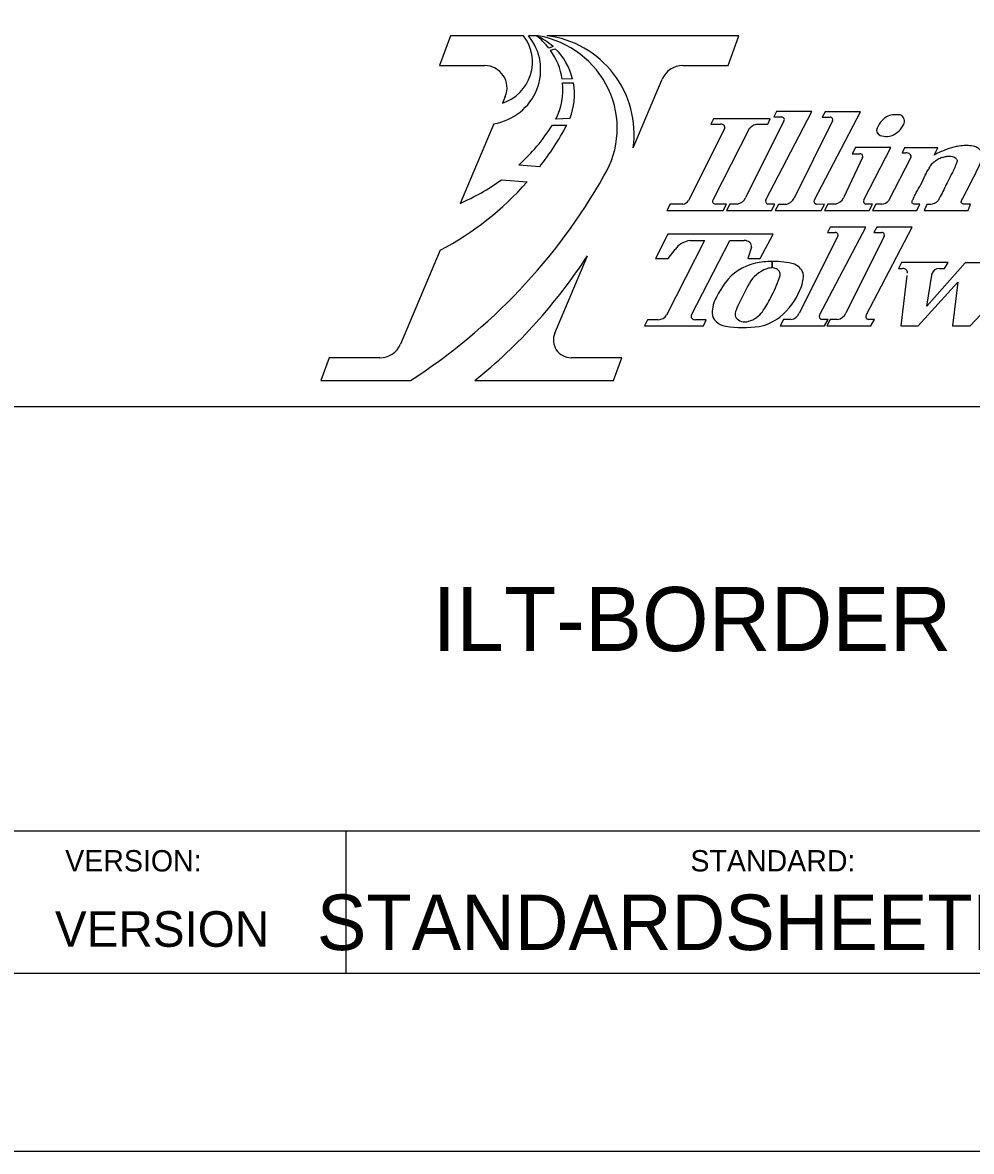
# Model space of a CAD drawing. Extents: x -0.22 to 2.83, y -0.07 to 1.83.
# Drawn here: x 2.4415 to 2.6636, y 0 to 0.2643 of the extents above; entities that cross this region are included whole.
import ezdxf

# ---------------------------------------------------------------- set-up
doc = ezdxf.new("R2010")
doc.units = 0
for name, color, linetype in [('SH_General_Details', 7, 'Continuous'), ('SH_General_Details_Sheet_Standard-ILTollway', 7, 'Continuous'), ('SH_General_Details_Title_Text-ILTollway', 7, 'Continuous'), ('SH_General_Details_Version_Text-ILTollway', 7, 'Continuous'), ('SH_Printer Plotting Border-ILTollway', 7, 'Continuous'), ('Sheets_General Details - Revisions', 7, 'Continuous')]:
    doc.layers.add(name, color=color, linetype=linetype)

msp = doc.modelspace()

# ---------------------------------------------------------------- linework, layer by layer
at = {"layer": 'SH_General_Details'}
for p, q in [((2.541678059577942, 0.26125465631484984), (2.5391048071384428, 0.25424934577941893)), ((2.558770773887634, 0.26125307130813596), (2.541678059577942, 0.26125465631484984)), ((2.5617576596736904, 0.2612526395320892), (2.5599128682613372, 0.2612529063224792)), ((2.5622159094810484, 0.26125257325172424), (2.5617576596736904, 0.2612526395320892)), ((2.6092131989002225, 0.2612457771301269), (2.564246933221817, 0.26125227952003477)), ((2.6066432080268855, 0.25424934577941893), (2.6092131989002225, 0.2612457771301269)), ((2.5656805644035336, 0.2587088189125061), (2.564693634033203, 0.2583604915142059)), ((2.5650607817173, 0.2578687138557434), (2.5662091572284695, 0.25821166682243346)), ((2.5391048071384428, 0.25424934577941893), (2.5496910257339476, 0.25424934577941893)), ((2.5960569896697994, 0.25424934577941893), (2.6066432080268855, 0.25424934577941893)), ((2.570235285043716, 0.25119200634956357), (2.567815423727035, 0.251082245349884)), ((2.567924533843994, 0.2501808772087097), (2.5704507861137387, 0.25021086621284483)), ((2.584443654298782, 0.23498173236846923), (2.5912613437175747, 0.25107288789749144)), ((2.5544875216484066, 0.2470111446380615), (2.5538310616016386, 0.24545995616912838)), ((2.551788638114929, 0.24063379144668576), (2.5439024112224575, 0.221998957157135)), ((2.569615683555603, 0.24183801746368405), (2.5663216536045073, 0.24171894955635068)), ((2.616512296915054, 0.24179491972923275), (2.6032718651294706, 0.24179491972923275)), ((2.6197487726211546, 0.2413310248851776), (2.610752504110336, 0.22328553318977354)), ((2.615985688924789, 0.24053008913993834), (2.616512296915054, 0.24179491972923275)), ((2.6311086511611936, 0.24128882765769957), (2.622112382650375, 0.2232433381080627)), ((2.5655231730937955, 0.24031608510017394), (2.5688893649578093, 0.24028897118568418)), ((2.6058492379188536, 0.23947303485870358), (2.5973743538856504, 0.22265382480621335)), ((2.603179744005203, 0.22279209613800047), (2.6117820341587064, 0.23965211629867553)), ((2.613987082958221, 0.24053468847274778), (2.615985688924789, 0.24053008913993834)), ((2.6381201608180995, 0.23271397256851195), (2.633689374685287, 0.22326657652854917)), ((2.6494769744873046, 0.23273907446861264), (2.6442469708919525, 0.2225763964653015)), ((2.647989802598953, 0.2350050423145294), (2.6474070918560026, 0.23379013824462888)), ((2.6474070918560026, 0.23379013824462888), (2.648289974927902, 0.23379013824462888)), ((2.655788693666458, 0.2350050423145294), (2.647989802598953, 0.2350050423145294)), ((2.6549143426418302, 0.233294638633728), (2.655788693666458, 0.2350050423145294)), ((2.56256064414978, 0.23056123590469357), (2.5576849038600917, 0.23094110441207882)), ((2.5535774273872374, 0.22753960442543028), (2.559652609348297, 0.22704168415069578)), ((2.6615555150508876, 0.22308809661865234), (2.6636318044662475, 0.22710824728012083)), ((2.5931374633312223, 0.22180414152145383), (2.59234472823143, 0.22033744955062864)), ((2.59234472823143, 0.22033744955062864), (2.605503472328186, 0.22033744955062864)), ((2.5960391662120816, 0.2218161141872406), (2.5931374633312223, 0.22180414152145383)), ((2.6062812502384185, 0.22180450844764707), (2.603693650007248, 0.22180450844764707)), ((2.605503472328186, 0.22033744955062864), (2.6062812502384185, 0.22180450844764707)), ((2.607087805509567, 0.2218036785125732), (2.6062950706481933, 0.22033698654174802)), ((2.6062950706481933, 0.22033698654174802), (2.6168223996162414, 0.22032778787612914)), ((2.608808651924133, 0.2218008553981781), (2.607087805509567, 0.2218036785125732)), ((2.6176034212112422, 0.22180262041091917), (2.6160084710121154, 0.22181677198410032)), ((2.6168223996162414, 0.22032778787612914), (2.6176034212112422, 0.22180262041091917)), ((2.618447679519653, 0.2217614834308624), (2.6176549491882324, 0.22029479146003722)), ((2.6176549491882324, 0.22029479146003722), (2.6284404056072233, 0.22029142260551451)), ((2.6201685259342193, 0.22175866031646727), (2.618447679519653, 0.2217614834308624)), ((2.6292331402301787, 0.2217581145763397), (2.6273683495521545, 0.2217745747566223)), ((2.6284404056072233, 0.22029142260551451), (2.6292331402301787, 0.2217581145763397)), ((2.6300077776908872, 0.22183038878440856), (2.629215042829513, 0.22036369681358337)), ((2.629231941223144, 0.22031802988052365), (2.6397115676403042, 0.22031637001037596)), ((2.6317455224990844, 0.22178189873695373), (2.6300246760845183, 0.22178472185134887)), ((2.640502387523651, 0.22178071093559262), (2.6389453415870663, 0.22179781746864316)), ((2.6397115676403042, 0.22031637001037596), (2.640502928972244, 0.22178052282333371)), ((2.6412836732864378, 0.22180444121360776), (2.6404826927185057, 0.22033670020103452)), ((2.6404826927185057, 0.22033670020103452), (2.650853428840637, 0.22033670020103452)), ((2.642634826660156, 0.22180444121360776), (2.6412836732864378, 0.22180444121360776)), ((2.6515525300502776, 0.221801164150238), (2.6502094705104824, 0.221801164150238)), ((2.650853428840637, 0.22033670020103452), (2.6515525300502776, 0.221801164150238)), ((2.6531976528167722, 0.22174590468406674), (2.652547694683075, 0.22033670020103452)), ((2.652547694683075, 0.22033670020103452), (2.662856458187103, 0.22033670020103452)), ((2.6634214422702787, 0.2218007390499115), (2.6617628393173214, 0.22181180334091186)), ((2.662856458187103, 0.22033670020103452), (2.6634214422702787, 0.2218007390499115)), ((2.6323300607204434, 0.21430038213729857), (2.6233337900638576, 0.19625489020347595)), ((2.6432246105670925, 0.21430038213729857), (2.6342283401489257, 0.19625489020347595)), ((2.598115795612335, 0.1958784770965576), (2.6070817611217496, 0.2133110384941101)), ((2.6070817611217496, 0.2133110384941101), (2.610442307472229, 0.2133110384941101)), ((2.5392720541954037, 0.21105761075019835), (2.529944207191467, 0.18901628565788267)), ((2.5660758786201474, 0.19162998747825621), (2.573748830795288, 0.20973973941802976)), ((2.592641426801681, 0.20907231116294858), (2.594264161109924, 0.21120603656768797)), ((2.6170039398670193, 0.2083940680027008), (2.6170039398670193, 0.20687558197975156)), ((2.6170039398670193, 0.20687558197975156), (2.6170039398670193, 0.2083940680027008)), ((2.6666739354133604, 0.2080908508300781), (2.6621581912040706, 0.2080908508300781)), ((2.663346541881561, 0.19334409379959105), (2.6746359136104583, 0.20542692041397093)), ((2.6196690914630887, 0.19477303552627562), (2.6188763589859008, 0.193306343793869)), ((2.6188763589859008, 0.193306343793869), (2.6292116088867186, 0.19333077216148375)), ((2.6213899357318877, 0.19477021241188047), (2.6196690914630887, 0.19477303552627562)), ((2.630071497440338, 0.19479352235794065), (2.6285897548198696, 0.1947861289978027)), ((2.6292116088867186, 0.19333077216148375), (2.630071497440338, 0.19479352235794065)), ((2.6305636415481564, 0.19477303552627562), (2.6297709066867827, 0.193306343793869)), ((2.6297709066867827, 0.193306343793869), (2.6401061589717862, 0.19333077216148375)), ((2.6322844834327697, 0.19477021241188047), (2.6305636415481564, 0.19477303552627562)), ((2.6409660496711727, 0.19479352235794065), (2.639484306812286, 0.1947861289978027)), ((2.6401061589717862, 0.19333077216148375), (2.6409660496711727, 0.19479352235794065)), ((2.6591873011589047, 0.19334409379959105), (2.663346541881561, 0.19334409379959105)), ((2.513288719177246, 0.18583782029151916), (2.5113223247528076, 0.1804845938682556)), ((2.5251477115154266, 0.18583782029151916), (2.513288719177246, 0.18583782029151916)), ((2.581771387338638, 0.18583782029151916), (2.5699123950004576, 0.18583782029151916)), ((2.579804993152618, 0.1804845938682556), (2.581771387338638, 0.18583782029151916)), ((2.5113223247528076, 0.1804845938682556), (2.53227757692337, 0.1804845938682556)), ((2.547344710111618, 0.1804845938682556), (2.579804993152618, 0.1804845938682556)), ((2.7916666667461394, 0.17433751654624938), (2.4316674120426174, 0.17433751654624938)), ((2.7916666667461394, 0.07499986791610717), (2.4316674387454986, 0.07499986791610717)), ((2.517257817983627, 0.04166668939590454), (2.517257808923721, 0.07499986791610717))]:
    msp.add_line(p, q, dxfattribs=at)
msp.add_lwpolyline([(0.1666666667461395, 0.0416666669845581), (0.1666666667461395, 1.791666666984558), (2.7916666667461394, 1.791666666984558), (2.7916666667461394, 0.0416666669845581)], close=True, dxfattribs=at)
for points in [[(2.6155131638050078, 0.22285597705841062), (2.6262976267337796, 0.2434896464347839), (2.61800227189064, 0.2434869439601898)], [(2.61800227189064, 0.2434869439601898), (2.6173446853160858, 0.24223627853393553), (2.6191797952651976, 0.24223627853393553)], [(2.626873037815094, 0.22281378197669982), (2.6376575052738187, 0.24344744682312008), (2.629362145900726, 0.24344474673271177)], [(2.629362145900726, 0.24344474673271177), (2.628704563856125, 0.2421940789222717)], [(2.5663006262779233, 0.2417181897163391), (2.5663148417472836, 0.24171870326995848), (2.5663184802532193, 0.24171883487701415)], [(2.5663216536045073, 0.24171894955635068), (2.5663150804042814, 0.2417120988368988)], [(2.5663184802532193, 0.24171883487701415), (2.5663216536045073, 0.24171894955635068)], [(2.6032718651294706, 0.24179491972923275), (2.6026142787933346, 0.2405442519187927)], [(2.6026142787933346, 0.2405442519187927), (2.6048686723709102, 0.2405442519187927)], [(2.628704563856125, 0.2421940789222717), (2.6305396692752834, 0.2421940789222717)], [(2.636509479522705, 0.23505239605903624), (2.6357160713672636, 0.23361922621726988), (2.6375511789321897, 0.23361922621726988)], [(2.638450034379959, 0.22283702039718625), (2.644804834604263, 0.23505509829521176), (2.636509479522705, 0.23505239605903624)], [(2.612125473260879, 0.21171108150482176), (2.6113013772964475, 0.20911943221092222), (2.6141857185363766, 0.20911943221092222), (2.6171877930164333, 0.21477393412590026), (2.5925825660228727, 0.21477393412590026), (2.5896982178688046, 0.20907231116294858), (2.592641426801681, 0.20907231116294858)], [(2.6280944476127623, 0.19582533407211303), (2.6388789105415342, 0.21645900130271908), (2.6305835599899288, 0.21645630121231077)], [(2.6305835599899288, 0.21645630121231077), (2.629925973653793, 0.2152056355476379), (2.6317610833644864, 0.2152056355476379)], [(2.6389889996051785, 0.19582533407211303), (2.649773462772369, 0.21645900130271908), (2.641478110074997, 0.21645630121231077)], [(2.641478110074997, 0.21645630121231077), (2.6408205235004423, 0.2152056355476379), (2.6426556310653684, 0.2152056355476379)], [(2.5977626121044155, 0.21331319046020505), (2.601117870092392, 0.21331319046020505), (2.592229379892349, 0.19583135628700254)], [(2.6473037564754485, 0.20813842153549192), (2.64659074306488, 0.20675888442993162), (2.6474820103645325, 0.20675888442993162)], [(2.6560975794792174, 0.20675888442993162), (2.657345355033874, 0.20675888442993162), (2.6581772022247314, 0.20813842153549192), (2.6473037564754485, 0.20813842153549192)], [(2.6621581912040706, 0.2080908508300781), (2.6531861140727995, 0.1979108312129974)], [(2.6485515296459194, 0.20509393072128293), (2.6471255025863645, 0.19334409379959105), (2.651165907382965, 0.19334409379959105)], [(2.6531861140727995, 0.1979108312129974), (2.6544338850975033, 0.20561720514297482)], [(2.651165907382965, 0.19334409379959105), (2.660435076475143, 0.20352411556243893), (2.6591873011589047, 0.19334409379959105)], [(2.5902868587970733, 0.19474757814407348), (2.5877556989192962, 0.19474757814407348), (2.5871081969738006, 0.19333395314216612), (2.6008824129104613, 0.19333395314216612), (2.601529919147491, 0.19474757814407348), (2.5989987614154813, 0.19474757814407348)]]:
    msp.add_lwpolyline(points, dxfattribs=at)
for centre, radius, start, end in [((2.5507281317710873, 0.255099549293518), 0.010126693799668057, 287.8430702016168, 37.42003830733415), ((2.5556024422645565, 0.24746375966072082), 0.01510032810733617, 48.13245664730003, 65.94449523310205), ((2.5523351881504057, 0.24875107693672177), 0.015654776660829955, 37.86715463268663, 52.99453830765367), ((2.5614015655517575, 0.23816590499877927), 0.02326105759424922, 352.1321590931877, 82.97379849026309), ((2.5523351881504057, 0.24875107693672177), 0.015654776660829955, 8.563821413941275, 35.620851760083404), ((2.5556024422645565, 0.24746375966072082), 0.01510032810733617, 14.2940508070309, 45.378821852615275), ((2.5496910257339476, 0.24904101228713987), 0.005208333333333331, 337.0620105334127, 90), ((2.5960569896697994, 0.24904101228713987), 0.005208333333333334, 89.99999999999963, 157.0380282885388), ((2.5523351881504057, 0.24875107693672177), 0.015654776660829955, 333.3076244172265, 5.240307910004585), ((2.5556024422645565, 0.24746375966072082), 0.01510032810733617, 338.1265619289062, 10.481826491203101), ((2.5249901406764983, 0.26624088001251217), 0.04811467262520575, 312.80595253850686, 327.3971515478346), ((2.506296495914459, 0.2740884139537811), 0.07113557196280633, 322.2736785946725, 331.63145455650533), ((2.4574629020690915, 0.29661533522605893), 0.13814334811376, 302.79076806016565, 330.41292215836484), ((2.5249901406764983, 0.26624088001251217), 0.04811467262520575, 293.1454474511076, 306.45199352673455), ((2.506296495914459, 0.2740884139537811), 0.07113557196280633, 297.6170242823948, 318.5957779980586), ((2.469345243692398, 0.2774257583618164), 0.1244247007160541, 308.8203728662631, 327.04420513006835), ((2.5699123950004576, 0.19000448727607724), 0.004166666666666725, 157.03802828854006, 270), ((2.5251477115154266, 0.1910461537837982), 0.005208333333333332, 270.00000000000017, 337.0620105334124)]:
    msp.add_arc(centre, radius, start, end, dxfattribs=at)
for centre, major_axis, ratio, start_param, end_param in [((2.5495658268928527, 0.2532761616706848), (0.0132138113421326, 0), 0.9705854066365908, 4.8814113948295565, 6.954431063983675), ((2.5579672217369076, 0.23956523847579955), (0.022744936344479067, 0), 0.9705854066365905, 5.75331709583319, 7.666080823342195), ((2.566307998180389, 0.24171546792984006), (7.887166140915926e-06, 0), 0.9705854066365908, 2.778111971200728, 5.827459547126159), ((2.604906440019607, 0.23974349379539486), (0.0010015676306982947, -2.4531331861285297e-19), 0.8000752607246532, 5.938912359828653, 7.891702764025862), ((2.6190690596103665, 0.2416246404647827), (0.0007724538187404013, -1.8919661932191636e-19), 0.800075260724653, 5.788124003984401, 7.71013160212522), ((2.6304289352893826, 0.2415824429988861), (0.0007724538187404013, -1.8919661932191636e-19), 0.800075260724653, 5.788124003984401, 7.71013160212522), ((2.649391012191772, 0.2375553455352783), (-0.008237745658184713, 1.0088328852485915e-18), 0.8000752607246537, 5.657384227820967, 5.961923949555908), ((2.641774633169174, 0.24230186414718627), (0.006436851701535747, -1.5765739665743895e-18), 0.8000752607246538, 5.35994097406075, 5.975474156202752), ((2.643243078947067, 0.2390981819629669), (-0.00179891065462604, 2.2030301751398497e-19), 0.8000752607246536, 5.899852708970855, 7.2592592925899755), ((2.6436369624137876, 0.24040055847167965), (-0.003418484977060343, 4.1864366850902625e-19), 0.800075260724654, 1.1482793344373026, 2.20319774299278), ((2.637440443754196, 0.23300758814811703), (0.0007724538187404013, -1.8919661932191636e-19), 0.800075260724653, 5.788124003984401, 7.71013160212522), ((2.6484939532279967, 0.23298302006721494), (-0.0010292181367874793, 1.2604286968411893e-19), 0.8000752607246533, 2.840833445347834, 4.911898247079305), ((2.5958096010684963, 0.2231503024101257), (0.0016833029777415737, -4.122903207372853e-19), 0.8000752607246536, 4.8491919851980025, 5.905635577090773), ((2.603823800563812, 0.22242724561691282), (-0.0007891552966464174, 9.664365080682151e-20), 0.8000752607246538, 5.667079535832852, 7.688297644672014), ((2.607959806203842, 0.2240691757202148), (0.0029594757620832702, -7.2486250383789e-19), 0.8000752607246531, 5.00329646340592, 5.945866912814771), ((2.6163459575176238, 0.22251490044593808), (-0.0009355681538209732, 1.1457405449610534e-19), 0.8000752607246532, 5.810064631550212, 7.4849317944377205), ((2.619319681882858, 0.22402697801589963), (0.0029594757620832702, -7.2486250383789e-19), 0.8000752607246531, 5.00329646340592, 5.945866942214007), ((2.6277058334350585, 0.2224727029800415), (-0.0009355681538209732, 1.1457405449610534e-19), 0.8000752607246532, 5.810064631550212, 7.48493146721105), ((2.6308966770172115, 0.22405021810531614), (0.0029594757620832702, -7.2486250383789e-19), 0.8000752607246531, 5.003296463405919, 5.945867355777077), ((2.6392828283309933, 0.222495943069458), (-0.0009355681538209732, 1.1457405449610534e-19), 0.8000752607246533, 5.810064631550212, 7.484931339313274), ((2.6421507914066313, 0.22391506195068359), (0.00268206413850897, -6.569162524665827e-19), 0.8000752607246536, 4.893854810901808, 5.609542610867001), ((2.6316503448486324, 0.21459399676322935), (0.0007724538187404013, -1.8919661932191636e-19), 0.800075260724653, 5.788124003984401, 7.71013160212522), ((2.6425448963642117, 0.2145939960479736), (0.0007724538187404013, -1.8919661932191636e-19), 0.800075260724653, 5.788124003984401, 7.71013160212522), ((2.5988792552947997, 0.20921383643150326), (-0.005243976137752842, 6.422018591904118e-19), 0.8000752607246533, 4.92697049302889, 5.7884101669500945), ((2.6104337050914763, 0.2119385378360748), (0.0017154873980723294, -4.201732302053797e-19), 0.8000752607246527, 6.116694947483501, 7.848967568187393), ((2.616626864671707, 0.19869619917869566), (-0.012129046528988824, 1.4853798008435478e-18), 0.8000752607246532, 5.01078761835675, 5.765691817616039), ((2.6195860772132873, 0.2004766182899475), (-0.008689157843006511, 1.0641149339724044e-18), 0.8000752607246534, 5.175654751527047, 5.860096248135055), ((2.6171590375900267, 0.19548105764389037), (-0.016140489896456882, 1.9766399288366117e-18), 0.8000752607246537, 4.721998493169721, 4.969094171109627), ((2.6167585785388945, 0.20490928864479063), (-0.0024698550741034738, 3.024700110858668e-19), 0.8000752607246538, 4.612883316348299, 5.153926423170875), ((2.6171590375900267, 0.19548105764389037), (-0.016140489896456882, 1.9766399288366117e-18), 0.8000383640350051, 4.395078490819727, 4.7149049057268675), ((2.6167585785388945, 0.20490928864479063), (-0.0024698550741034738, 3.024700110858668e-19), 0.8000752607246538, 4.071840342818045, 4.566171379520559), ((2.616702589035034, 0.20525218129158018), (0.002180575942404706, -5.340870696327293e-19), 0.8000752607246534, 5.909204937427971, 7.074943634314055), ((2.620201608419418, 0.20487194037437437), (0.004112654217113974, -1.0073097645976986e-18), 0.8000752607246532, 0.08712246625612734, 1.0647598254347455), ((2.6475526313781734, 0.20587112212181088), (-0.0011118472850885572, 1.3616202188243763e-19), 0.8000752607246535, 2.93516670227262, 4.775951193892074), ((2.6561704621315, 0.20534410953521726), (-0.0017698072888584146, 2.1673888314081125e-19), 0.800075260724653, 4.753581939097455, 6.089103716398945), ((2.565342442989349, 0.21723486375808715), (0.0556713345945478, -1.3635544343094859e-17), 0.8000752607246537, 5.883899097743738, 5.995916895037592), ((2.611839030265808, 0.20521104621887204), (0.012459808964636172, -3.051773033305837e-18), 0.8000752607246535, 5.922241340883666, 6.277888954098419), ((2.6329956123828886, 0.19068926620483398), (-0.03131109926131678, 3.8345037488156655e-18), 0.8000752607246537, 5.7465390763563, 5.900046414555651), ((2.7141161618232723, 0.16679252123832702), (-0.11217070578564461, 1.3736949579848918e-17), 0.8000752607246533, 5.863868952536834, 5.924634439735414), ((2.6045524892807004, 0.20649450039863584), (0.019872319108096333, -4.867314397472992e-18), 0.8000752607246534, 5.5091350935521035, 5.976236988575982), ((2.613942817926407, 0.19639452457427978), (-0.01098572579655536, 1.3453633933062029e-18), 0.8000752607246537, 5.853724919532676, 6.297771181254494), ((2.5899682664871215, 0.20798209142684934), (0.028507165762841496, -6.98224186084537e-18), 0.8000752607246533, 5.76243947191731, 5.92185011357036), ((2.590139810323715, 0.19657253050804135), (0.0022857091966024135, -5.598372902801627e-19), 0.8000752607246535, 4.776767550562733, 5.865888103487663), ((2.598944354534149, 0.19550648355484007), (-0.000950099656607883, 1.1635365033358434e-19), 0.8000752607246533, 5.771816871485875, 7.911274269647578), ((2.606946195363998, 0.1963254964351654), (-0.0039886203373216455, 4.88465112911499e-19), 0.8000752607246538, 0.018542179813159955, 1.3534190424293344), ((2.609394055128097, 0.19890387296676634), (0.006013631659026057, -1.4729149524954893e-18), 0.8000752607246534, 5.063271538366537, 5.7920136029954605), ((2.6205410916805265, 0.19703853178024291), (0.0029594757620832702, -7.2486250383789e-19), 0.8000752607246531, 5.00329646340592, 5.945867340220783), ((2.6289272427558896, 0.19548425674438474), (-0.0009355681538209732, 1.1457405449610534e-19), 0.8000752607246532, 5.810064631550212, 7.484931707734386), ((2.6314356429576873, 0.19703853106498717), (0.0029594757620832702, -7.2486250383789e-19), 0.8000752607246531, 5.00329646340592, 5.945867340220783), ((2.6398217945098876, 0.19548425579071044), (-0.0009355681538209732, 1.1457405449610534e-19), 0.8000752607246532, 5.810064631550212, 7.484931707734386), ((2.610179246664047, 0.21168625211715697), (0.023453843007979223, -5.744534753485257e-18), 0.8000752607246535, 4.536965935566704, 4.873723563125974), ((2.6105971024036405, 0.1961409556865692), (-0.002357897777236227, 2.887591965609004e-19), 0.8000752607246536, 0.5153538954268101, 1.9459629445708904), ((2.611501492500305, 0.2010271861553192), (0.010126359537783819, -2.480242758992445e-18), 0.8000752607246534, 4.9562759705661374, 5.511991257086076)]:
    msp.add_ellipse(centre, major_axis=major_axis, ratio=ratio, start_param=start_param, end_param=end_param, dxfattribs=at)
for points in [[(2.647909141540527, 0.24074205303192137), (2.647969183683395, 0.24139097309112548), (2.6477590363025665, 0.24203988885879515), (2.6471586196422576, 0.2426167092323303), (2.646257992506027, 0.2427609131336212), (2.644786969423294, 0.24264074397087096), (2.6434360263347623, 0.2420158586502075), (2.642714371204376, 0.24141589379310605)], [(2.6117820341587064, 0.23965211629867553), (2.6127008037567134, 0.24036657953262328), (2.613987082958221, 0.24053468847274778)], [(2.6636318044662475, 0.22710824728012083), (2.665756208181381, 0.2314826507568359), (2.6661532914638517, 0.23283391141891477), (2.6660341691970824, 0.23399440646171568), (2.665835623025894, 0.23431235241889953), (2.665279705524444, 0.23483696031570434), (2.664465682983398, 0.23528208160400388), (2.662897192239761, 0.23552054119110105), (2.66228171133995, 0.2355682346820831), (2.6615669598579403, 0.23550464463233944), (2.660038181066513, 0.23528208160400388), (2.657933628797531, 0.23466209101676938), (2.6565209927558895, 0.23410625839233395), (2.6549143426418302, 0.233294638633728)], [(2.6528441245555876, 0.22856152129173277), (2.6533814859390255, 0.22962547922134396), (2.653890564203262, 0.23045174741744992), (2.654413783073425, 0.2313006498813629), (2.6549087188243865, 0.2317194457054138), (2.6557713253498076, 0.23235329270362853), (2.65683190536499, 0.232783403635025), (2.6577793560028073, 0.23299845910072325), (2.658585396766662, 0.23305505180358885), (2.659207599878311, 0.23297582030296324), (2.6597449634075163, 0.2327381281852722), (2.6600136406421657, 0.23252307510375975), (2.660282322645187, 0.231855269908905), (2.6599853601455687, 0.23105163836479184), (2.6594762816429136, 0.2297952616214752), (2.658910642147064, 0.22871998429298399)], [(2.6502094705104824, 0.221801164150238), (2.6500305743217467, 0.22187633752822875), (2.649816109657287, 0.22199984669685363), (2.6497217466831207, 0.22226745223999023), (2.6497732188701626, 0.222569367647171), (2.6499734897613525, 0.22291086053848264), (2.6502280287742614, 0.22347679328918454), (2.650737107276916, 0.22454075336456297), (2.651811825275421, 0.22644229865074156), (2.6528441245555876, 0.22856152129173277)], [(2.658910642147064, 0.22871998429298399), (2.6579490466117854, 0.22679405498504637), (2.6571571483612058, 0.22518679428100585), (2.656336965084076, 0.22360217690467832), (2.656025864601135, 0.2230136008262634), (2.6557713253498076, 0.2225608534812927), (2.6552622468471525, 0.22213074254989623), (2.6548945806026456, 0.221949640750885), (2.6544420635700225, 0.22179118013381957), (2.6531976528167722, 0.22174590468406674)], [(2.6617628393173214, 0.22181180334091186), (2.6615458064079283, 0.2218943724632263), (2.6612639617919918, 0.22218026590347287), (2.6613205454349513, 0.22258625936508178), (2.6615555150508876, 0.22308809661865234)], [(2.6085454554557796, 0.195211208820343), (2.6084574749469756, 0.1954600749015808), (2.608442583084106, 0.19656918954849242), (2.608710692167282, 0.19726089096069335), (2.609078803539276, 0.19828562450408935)]]:
    msp.add_spline(points, degree=3, dxfattribs=at)
at = {"layer": 'SH_Printer Plotting Border-ILTollway'}
msp.add_lwpolyline([(0, 1.833282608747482), (2.833327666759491, 1.833282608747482), (2.833327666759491, 0), (0, 0)], close=True, dxfattribs=at)

# ---------------------------------------------------------------- texts
at = {"layer": 'SH_General_Details'}
msp.add_text('VERSION:', height=0.004999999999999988, rotation=1.0784289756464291e-05, dxfattribs=at).set_placement((2.45144259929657, 0.06555551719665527))
at = {"layer": 'SH_General_Details_Sheet_Standard-ILTollway'}
msp.add_text('STANDARDSHEETBORDER', height=0.013, dxfattribs=at).set_placement((2.510364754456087, 0.047145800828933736))
at = {"layer": 'SH_General_Details_Title_Text-ILTollway'}
msp.add_text('ILT-BORDER', height=0.014999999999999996, dxfattribs=at).set_placement((2.5374648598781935, 0.11716869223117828))
at = {"layer": 'SH_General_Details_Version_Text-ILTollway'}
msp.add_text('VERSION', height=0.008333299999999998, dxfattribs=at).set_placement((2.449036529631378, 0.047916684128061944))
at = {"layer": 'Sheets_General Details - Revisions'}
msp.add_text('STANDARD:', height=0.004999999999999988, rotation=1.0784289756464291e-05, dxfattribs=at).set_placement((2.5978434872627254, 0.06555551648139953))

doc.saveas('drawing.dxf')
